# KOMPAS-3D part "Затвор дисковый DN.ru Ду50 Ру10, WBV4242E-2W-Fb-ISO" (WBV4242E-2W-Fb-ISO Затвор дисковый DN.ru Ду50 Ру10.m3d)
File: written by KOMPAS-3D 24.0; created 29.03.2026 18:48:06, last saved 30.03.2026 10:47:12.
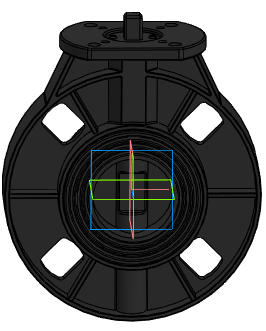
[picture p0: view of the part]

Document properties: Автор: R2D2; Полное имя файла: WBV4242E-2W-Fb-ISO Затвор дисковый DN.ru Ду50 Ру10.cdw

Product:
- Part/product: Затвор дисковый DN.ru Ду50 Ру10  | designation WBV4242E-2W-Fb-ISO
    Масса: 0.85
    Раздел спецификации: Прочие изделия
    Форматы листов документа: A2
    Примечание: D050-81204

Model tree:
1. Операция без истории:1

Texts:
  WBV4242E-2W-Fb-ISO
